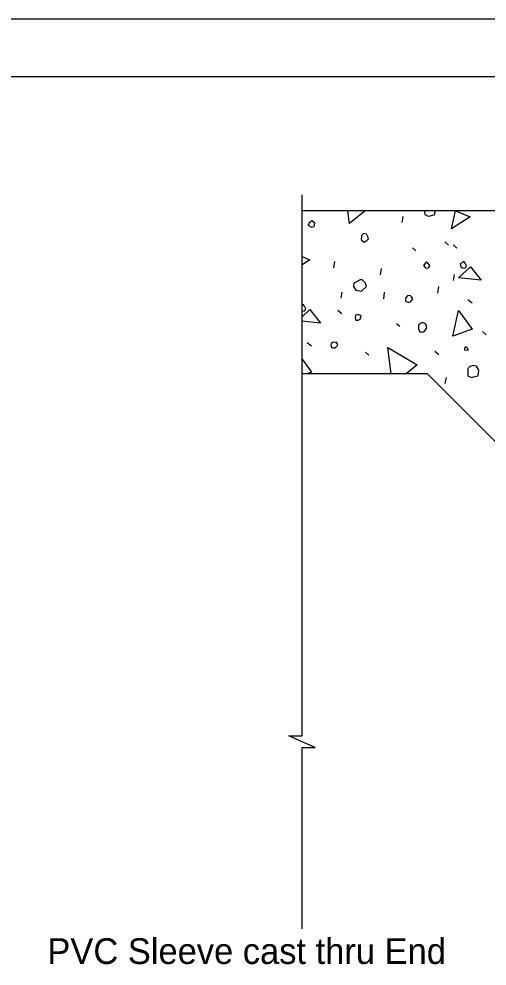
# Model space of a CAD drawing. Extents: x 0 to 30.8, y 0 to 21.2.
# Drawn here: x 19.36 to 22.1, y 14.24 to 19.8 of the extents above; entities that cross this region are included whole.
import ezdxf

# ---------------------------------------------------------------- set-up
doc = ezdxf.new("R2010")
doc.units = 0
for name, color, linetype in [('ActivePts-ConstElements', 7, 'Continuous'), ('Dimension', 7, 'Continuous'), ('Miscellaneous', 7, 'Continuous'), ('Miscellaneous1', 7, 'Continuous'), ('SupstrConc', 7, 'Continuous')]:
    doc.layers.add(name, color=color, linetype=linetype)

msp = doc.modelspace()

# ---------------------------------------------------------------- linework, layer by layer
at = {"layer": 'ActivePts-ConstElements'}
msp.add_lwpolyline([(0, 0), (30.7879, 0), (30.7879, 19.4596), (0, 19.4596)], close=True, dxfattribs=at)
at = {"layer": 'Dimension'}
msp.add_lwpolyline([(21.0171, 14.4602), (21.0171, 15.5245), (21.0946, 15.5245), (21.0171, 15.5582), (20.9396, 15.592), (21.0171, 15.592), (21.0171, 18.7684)], dxfattribs=at)
at = {"layer": 'Miscellaneous'}
for p, q in [((21.604, 18.6062), (21.6101, 18.6415)), ((21.6647, 18.4569), (21.6851, 18.439)), ((21.8546, 18.4922), (21.8755, 18.4719)), ((21.9034, 18.4742), (21.9243, 18.4539)), ((21.2046, 18.3387), (21.2101, 18.3764)), ((21.477, 18.2978), (21.4824, 18.3355)), ((21.9051, 18.265), (21.9112, 18.3003)), ((21.247, 18.1612), (21.2531, 18.1964)), ((21.4963, 18.1581), (21.5018, 18.1958)), ((21.8135, 18.1913), (21.819, 18.229)), ((21.9894, 18.153), (22.0152, 18.1341)), ((21.227, 18.0911), (21.2504, 18.0715)), ((21.5715, 18.0126), (21.5912, 17.9972)), ((22.0757, 17.9665), (22.0966, 17.9462)), ((21.0477, 17.9007), (21.0734, 17.8817)), ((21.3888, 17.8446), (21.4091, 17.8267)), ((21.7962, 17.8502), (21.8196, 17.8306)), ((21.8577, 17.6596), (21.8637, 17.6949))]:
    msp.add_line(p, q, dxfattribs=at)
for points in [[(21.2955, 18.5986), (21.2858, 18.6747)], [(21.3878, 18.6747), (21.2955, 18.5986)], [(21.736, 18.6747), (21.7367, 18.6521), (21.7574, 18.6422), (21.7695, 18.6454), (21.7961, 18.6525), (21.799, 18.6747)], [(21.8939, 18.5674), (21.917, 18.6746), (22.0043, 18.6384), (21.8939, 18.5674)], [(21.0549, 18.5885), (21.0733, 18.5779), (21.0877, 18.5818), (21.0929, 18.6013), (21.0739, 18.6143), (21.0655, 18.6069), (21.0565, 18.6019), (21.0549, 18.5885), (21.0536, 18.5933)], [(21.3653, 18.5216), (21.365, 18.5034), (21.3816, 18.4897), (21.3972, 18.499), (21.4073, 18.5095), (21.4041, 18.5216), (21.3947, 18.5372), (21.3783, 18.5406), (21.3658, 18.5294), (21.3653, 18.5216)], [(21.0171, 18.4049), (21.0625, 18.3861), (21.0171, 18.3569)], [(21.729, 18.3524), (21.7431, 18.3381), (21.7583, 18.3396), (21.766, 18.3494), (21.7647, 18.3542), (21.756, 18.3674), (21.7444, 18.3721), (21.7367, 18.3622), (21.729, 18.3524)], [(21.9345, 18.2807), (22.005, 18.3461), (22.0676, 18.2671), (21.9345, 18.2807)], [(21.948, 18.3464), (21.9578, 18.3387), (21.9712, 18.3371), (21.9795, 18.3445), (21.9794, 18.3548), (21.9737, 18.3662), (21.9657, 18.377), (21.9525, 18.3683), (21.9441, 18.3609), (21.948, 18.3464)], [(21.3193, 18.2297), (21.333, 18.2075), (21.3652, 18.2032), (21.3945, 18.2291), (21.388, 18.2533), (21.3707, 18.2694), (21.358, 18.2686), (21.3376, 18.2579), (21.322, 18.2485), (21.3193, 18.2297)], [(21.0171, 18.0862), (21.0294, 18.0847), (21.0378, 18.0922), (21.0376, 18.1025), (21.0319, 18.1139), (21.0239, 18.1247), (21.0171, 18.1202)], [(21.6248, 18.1615), (21.6245, 18.1433), (21.6423, 18.1351), (21.6561, 18.1414), (21.6674, 18.1573), (21.6593, 18.1681), (21.6525, 18.1741), (21.6416, 18.1763), (21.6367, 18.175), (21.6248, 18.1615)], [(21.0171, 18.051), (21.0632, 18.0938), (21.1258, 18.0148), (21.0171, 18.0258)], [(21.3296, 18.0461), (21.3335, 18.0316), (21.3462, 18.0325), (21.3577, 18.0381), (21.3634, 18.0552), (21.3567, 18.0611), (21.3451, 18.0658), (21.3306, 18.0619), (21.3296, 18.0461)], [(21.9021, 17.9381), (21.9341, 18.089), (22.0154, 17.9788), (21.9021, 17.9381)], [(21.7009, 18.0032), (21.6995, 17.9796), (21.7095, 17.9615), (21.727, 17.9637), (21.7384, 17.9693), (21.749, 17.9877), (21.7432, 18.0094), (21.7255, 18.0176), (21.7134, 18.0144), (21.7009, 18.0032)], [(21.1894, 17.874), (21.1955, 17.8704), (21.2113, 17.8695), (21.2239, 17.8806), (21.2268, 17.8891), (21.218, 17.9023), (21.1974, 17.902), (21.1891, 17.8946), (21.1868, 17.8836), (21.1894, 17.874)], [(21.5409, 17.7164), (21.5212, 17.8723), (21.6933, 17.7709), (21.6273, 17.7164)], [(21.9701, 17.858), (21.9914, 17.8559), (21.9888, 17.8656), (21.9808, 17.8764), (21.97, 17.8683), (21.9701, 17.858)], [(21.0171, 17.8031), (21.0736, 17.7265), (21.0457, 17.7164)], [(21.989, 17.7491), (21.9903, 17.7055), (22.0111, 17.6956), (22.0232, 17.6988), (22.0497, 17.7059), (22.054, 17.7381), (22.0397, 17.7627), (22.0208, 17.7655), (22.0015, 17.7603), (21.989, 17.7491)]]:
    msp.add_lwpolyline(points, dxfattribs=at)
at = {"layer": 'Miscellaneous1'}
msp.add_lwpolyline([(0, 19.8), (30.8, 19.8), (30.8, 0), (0, 0)], close=True, dxfattribs=at)
at = {"layer": 'SupstrConc'}
for p, q in [((25.794, 18.6747), (21.0171, 18.6747)), ((21.7523, 17.7164), (21.0171, 17.7164)), ((22.6273, 16.8414), (21.7523, 17.7164))]:
    msp.add_line(p, q, dxfattribs=at)

# ---------------------------------------------------------------- texts
at = {"layer": 'Dimension'}
msp.add_text('PVC Sleeve cast thru End ', height=0.1512, dxfattribs=at).set_placement((19.5237, 14.2535))

doc.saveas('drawing.dxf')
